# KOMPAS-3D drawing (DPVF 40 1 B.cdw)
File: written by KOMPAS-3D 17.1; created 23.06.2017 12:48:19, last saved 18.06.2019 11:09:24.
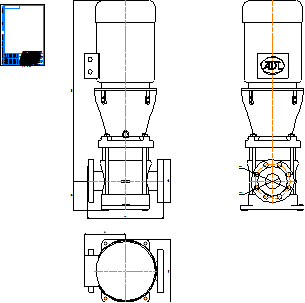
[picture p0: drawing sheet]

Sheet 1: A4, portrait

Title block, sheet 1: name: DPVF 40 1 B; material: Внимание! Данный продукт является объектом авторского права ООО «Торговый Дом АДЛ». / Запрещается изменение, копирование, распространение / (в том числе путем копирования на другие сайты и ресурсы в Интернете) / или любое иное использование информации и объектов без предварительного / согласия правообладателя (ООО «Торговый Дом АДЛ»).; scale: 1:1; sheets: 1; organisation: ООО "Торговый дом АДЛ"; sheet format: A4; stored path: C:\Клочков АВ\Насосы\DP PAMS\DPVF 40\Компас 2d\DPVF 40 1 B.cdw

Views: Спереди 1
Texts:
  Клочков АВ
  ООО АДЛ ГРУПП
Dimensions and other numbers on the sheet: 365; 197; 306; 209,6; 168,1; 76,2; 868,5; 140; 1:1; 1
